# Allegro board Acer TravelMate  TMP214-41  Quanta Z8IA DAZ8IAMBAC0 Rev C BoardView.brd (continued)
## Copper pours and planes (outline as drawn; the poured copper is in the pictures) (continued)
N18922914 on TOP (solid shape): 125.44,199.8 125.65,199.74 125.85,199.8 126.38,199.8 126.43,199.8 126.49,199.79 126.75,199.54 126.75,199.29 126.63,199.17 126.49,199.17 126.35,199.03 126.35,198.34 126.46,198.24 127.05,198.24 127.1,198.18 127.1,197.85 126.81,197.55 126.11,197.55 126.01,197.44 125.31,197.44 125.2,197.34 123.58,197.34 123.44,197.48 123.44,198.04 123.64,198.24 124.57,198.24 124.7,198.15 124.86,198.11 125.13,198.23 125.24,198.5 125.19,198.68 125.06,198.82 125.06,199.64 125.22,199.8
N22317721 on TOP (solid shape): 34.49,45.66 34.49,45.13 34.58,45.04 35.69,45.04 35.74,44.98 35.74,44.34 35.69,44.29 34.64,44.29 34.3,43.95 33.59,43.95 33.47,44.07 33.47,45.48 33.74,45.75 34.4,45.75
N22317721 on BOTTOM (solid shape): 34.51,45.67 34.51,44.14 34.31,43.94 32.46,43.94 32.14,44.26 32.14,45.18 32.72,45.77 34.41,45.77
N23734831 on BOTTOM (solid shape): 92.8,194.84 92.95,194.71 93.13,194.67 93.32,194.71 93.46,194.84 93.61,194.84 93.62,194.83 97.28,194.83 97.66,194.44 97.66,194.39 97.74,194.21 97.91,194.13 98.21,194.13 98.25,194.14 98.28,194.14 98.29,194.13 98.29,193.47 97.96,193.14 97.4,193.14 97.35,193.15 97.3,193.15 97.08,193.09 96.93,192.91 95.75,192.91 95.55,192.71 95.55,191.13 95.45,191.03 94.18,191.03 94.07,191.14 94.07,192.55 94.38,192.86 94.38,193.21 94.13,193.47 93.57,193.47 93.28,193.18 92.62,193.18 92.35,192.91 92.35,192.45 92.3,192.4 90.62,192.4 90.62,192.96 90.02,193.57 89.71,193.57 89.58,193.7 89.58,194.71 89.71,194.84
N24199172 on TOP (solid shape): 9.44,12.72 9.44,12.34 9.32,12.21 8.81,12.21 8.55,12.47 8.52,12.47 8.49,12.49 7.73,12.49 7.7,12.47 7.54,12.47 7.41,12.34 7.41,11.58 6.78,10.94 6.4,10.94 6.27,11.07 6.27,11.45 6.78,11.96 6.78,12.47 7.28,12.98 9.19,12.98
N24507636 on BOTTOM (solid shape): 9.7,41.18 9.7,37.11 10.08,36.73 11.22,36.73 11.98,35.96 11.98,35.71 11.86,35.58 11.35,35.58 11.2,35.43 8.43,35.43 8.3,35.56 8.3,35.84 8.3,35.84 8.17,35.96 8.17,37.49 7.08,37.49 6.83,37.23 6.32,37.23 6.07,37.48 6.07,38.26 6.46,38.26 6.54,38.28 6.6,38.35 6.62,38.35 6.78,38.5 6.78,39.65 6.9,39.77 8.17,39.77 8.3,39.9 8.3,41.17 8.56,41.43 9.44,41.43
N24690147 on TOP (solid shape): 130.35,187.73 130.35,187.47 130.09,187.22 129.33,187.22 129.2,187.09 129.2,186.84 129.08,186.71 128.82,186.71 128.57,186.97 128.57,187.73 128.7,187.86 130.22,187.86
N24742107 on TOP (solid shape): 95.46,187.12 95.68,187.05 95.9,187.12 96.15,187.12 96.17,187.11 96.26,187.08 96.35,187.07 96.44,187.08 96.53,187.11 96.54,187.12 96.69,187.12 96.99,186.81 96.99,186.61 97.07,186.43 97.25,186.36 97.44,186.36 97.55,186.25 97.55,185.66 96.77,184.88 96.69,184.88 96.68,184.89 96.58,184.94 96.46,184.96 96.34,184.94 96.23,184.88 95.17,184.88 95.07,184.98 95.07,185.07 95.76,185.07 95.76,185.27 95.07,185.27 95.07,185.57 95.13,185.57 95.14,185.56 95.25,185.5 95.37,185.48 95.75,185.86 95.37,186.24 95.29,186.23 95.21,186.21 95.11,186.21 95.07,186.3 95.07,187.05 95.11,187.06 95.18,187.08 95.25,187.12
N24742107 on BOTTOM (solid shape): 96.72,186.18 96.72,186.04 96.76,185.94 96.87,185.89 97.98,185.89 98.24,185.62 98.24,184.83 98.16,184.75 97.82,184.75 97.73,184.76 97.65,184.75 96.93,184.75 96.85,184.83 96.85,184.84 96.7,185.04 96.46,185.12 96.38,185.11 96.31,185.09 96.03,185.09 95.91,185.21 95.91,186.17 96.05,186.31 96.58,186.31
N24846908 on TOP (solid shape): 34.87,175.97 34.95,175.89 34.95,175.49 34.91,175.45 33.49,175.45 33.34,175.3 33.34,174.34 32.44,173.45 31.98,173.45 31.87,173.56 31.87,173.92 32.44,174.49 32.44,175.89 32.52,175.97 33.96,175.97
N24846932 on TOP (solid shape): 28.86,175.42 28.94,175.42 29.02,175.42 29.11,175.45 31.75,175.45 32.18,175.02 32.18,174.55 32.09,174.46 31.6,174.46 31.25,174.8 30.89,174.8 30.86,174.81 30.3,174.81 30.27,174.8 30.04,174.8 29.44,174.2 29.44,173.71 28.96,173.24 27.41,173.24 27.3,173.34 27.3,175.31 27.44,175.45 28.78,175.45
N24915888 on TOP (solid shape): 30.02,149.63 30.02,148.36 29.89,148.23 29.26,148.23 29.13,148.1 28.75,148.1 28.66,148.19 28.66,148.53 29.38,149.25 29.38,149.5 29.76,149.88
N25430994 on TOP (solid shape): 18.95,148.1 18.95,147.31 18.13,146.49 17.39,146.49 16.34,145.44 14.65,145.44 14.07,146.02 14.07,146.68 14.3,146.92 17.06,146.92 18.3,148.16 18.89,148.16
N26318025 on BOTTOM (solid shape): 36.88,194.33 36.88,193.44 36.11,192.68 34.59,192.68 34.34,192.43 34.24,192.38 34.2,192.27 34.2,191.61 34.08,191.49 33.5,191.49 33.32,191.67 33.32,192.81 33.7,193.19 35.35,193.19 35.48,193.32 35.48,194.33 35.61,194.46 36.75,194.46
N26402629 on TOP (solid shape): 38.76,136.83 38.75,136.8 38.74,136.77 38.74,136.74 38.74,136.36 38.77,136.27 38.84,136.21 38.87,136.2 38.87,135.42 38.76,135.31 38.01,135.31 37.78,135.07 37.78,134.09 38.07,133.79 38.99,133.79 39.11,133.66 39.11,132.4 39.02,132.31 35.26,132.31 34.97,132.59 34.97,135.23 34.42,135.78 34.42,136.73 34.56,136.87 38.72,136.87
N30140264 on TOP (solid shape): 150.54,213.76 151.43,213.76 151.58,213.61 151.58,213.59 151.67,213.36 151.86,213.2 151.86,213.04 151.94,212.96 151.94,210.97 152.32,210.59 152.32,209.06 152.19,208.94 151.68,208.94 151.56,209.06 151.56,210.21 151.18,210.59 151.18,211.48 151.43,211.73 151.43,212.75 151.31,212.87 151.31,212.88 151.16,213.08 150.92,213.15 150.85,213.15 150.78,213.13 149.65,213.13 149.47,213.31 149.47,213.92 150.39,213.92
N30330849 on TOP (solid shape): 162.86,164.68 163.43,164.68 163.75,164.36 163.75,162.33 167.05,159.03 167.05,155.71 166.99,155.6 166.97,155.47 166.99,155.35 167.04,155.24 167.16,155.13 167.3,155.07 167.32,155.07 167.56,154.83 167.56,153.31 168.67,152.2 168.67,150.29 168.42,150.04 167.36,150.04 167.34,150.06 167.29,150.1 167.23,150.11 166.57,150.11 166.53,150.1 166.49,150.09 166.43,150.07 166.37,150.1 166.33,150.13 166.28,150.16 166.18,150.21 166.06,150.23 165.86,150.18 165.72,150.04 164.86,150.04 164.76,150.14 164.76,151.63 164.92,151.79 164.92,151.96 164.92,151.96 164.92,154.47 165.26,154.82 165.26,157.46 165.27,157.46 165.27,157.48 163.77,158.98 161.72,158.98 161.21,159.48 161.21,161.06 160.57,161.69 159.18,161.69 159.05,161.82 159.05,165.12 159.3,165.38 162.16,165.38
N30330849 on BOTTOM (solid shape): outline of 110 points within 163.62,149.94 168.65,156.7
N30442036 on TOP (solid shape): 36.38,161.99 36.58,161.99 36.58,162.73 38.4,162.73 38.57,162.57 38.57,161.59 38.45,161.47 38.45,159.46 38.27,159.28 36.88,159.28 36.54,159.61 36.54,160.92 36.44,161.02 36.44,161.04 36.38,161.14 36.29,161.2 36.25,161.22 36.25,161.61 36.24,161.69 36.19,161.76 36.11,161.85 36.11,161.9 36.14,161.99 36.18,161.99 36.18,162.73 36.38,162.73
N30587125 on BOTTOM (solid shape): 57.58,182.04 57.58,180.46 58.9,179.14 59,179.14 59,178.33 58.31,178.33 58.31,179.04 57.65,179.7 56.87,179.7 56.76,179.8 56.76,182.06 57.55,182.06
N31076875 on BOTTOM (solid shape): 203.71,127.76 203.78,127.71 203.86,127.69 205.07,127.69 205.76,127 205.76,125.63 205.61,125.48 204.68,125.48 204.21,125.95 203.17,125.95 202.83,126.29 202.38,126.29 201.79,126.88 201.79,127.83 202.49,127.83 202.49,128.02 201.79,128.02 201.79,128.19 201.82,128.23 202.49,128.23 202.49,128.24 203.23,128.24
N31353100 on TOP (solid shape): 35.24,140.85 35.24,138.99 35.1,138.86 34.05,138.86 33.98,138.92 33.98,140.89 34.11,141.02 35.07,141.02
N31870175 on TOP (solid shape): 233.6,122.32 233.6,121.23 234.37,120.46 234.37,118.91 234.25,118.79 233.85,118.79 233.71,118.92 233.71,119.54 233.72,119.55 233.56,119.7 233.56,119.75 232.96,120.35 232.96,122.32 233.09,122.45 233.47,122.45
N32485009 on TOP (solid shape): 52.51,193.06 52.57,192.92 52.56,192.85 52.51,192.79 51.77,192.04 51.77,191.9 51.89,191.78 52.44,191.78 52.7,192.03 53.13,192.03 53.84,192.74 54.81,192.74 54.9,192.83 54.96,192.87 55.04,192.89 55.17,192.83 55.23,192.7 55.21,192.62 55.17,192.56 54.97,192.36 54,192.36 53.29,191.65 52.86,191.65 52.66,191.46 52.6,191.41 52.52,191.4 51.43,191.4 51.36,191.41 51.3,191.44 51.3,192.12 52.24,193.06 52.31,193.1 52.38,193.12
N33144601 on BOTTOM (solid shape): 221.15,123.94 221.15,123.34 221.03,123.21 218.53,123.21 218.43,123.31 218.43,123.93 218.51,124.01 221.08,124.01
N33144601 on BOTTOM (solid shape): 224.53,135.82 224.53,133.6 224.18,133.25 221.39,133.25 221.01,133.62 221.01,134.23 222.54,134.23 222.68,134.36 222.68,135.58 222.64,135.62 221.01,135.62 221.01,136.23 224.12,136.23
N33144601 on IN2 (solid shape): 224.58,134.08 224.58,128.55 221.2,125.17 221.2,123.39 221.03,123.21 219.88,123.21 219.76,123.34 219.76,125.76 222.82,128.83 222.82,134.15 223.01,134.34 224.33,134.34
N33147251 on TOP (solid shape): 89.3,175.33 89.3,175.26 89.25,175.21 88.79,175.21 88.62,175.03 88.62,173.68 88.18,173.25 88.18,171.98 88.06,171.85 87.42,171.85 87.29,171.98 87.29,172.74 87.55,173 87.55,174.24 87.68,174.37 87.98,174.37 88.22,174.61 88.22,174.8 88.26,174.84 88.26,175.38 89.25,175.38
N34933887 on BOTTOM (solid shape): 13.63,38.76 14.4,38.76 14.52,38.63 14.52,37.51 14.14,37.13 13.36,37.13 12.87,37.61 12.87,38.76 13,38.88 13.51,38.88
N35745601 on TOP (solid shape): 147.24,131.47 148.25,131.47 148.38,131.34 148.38,130.2 148.13,129.94 147.37,129.94 147.37,130.53 146.68,131.21 146.68,131.47 146.81,131.59 147.11,131.59
N36874581 on TOP (solid shape): 62.12,180.87 62.12,178.52 62.15,178.5 62.15,177.01 62.55,176.61 62.58,176.53 62.55,176.46 62.46,176.33 62.43,176.17 62.48,175.97 62.62,175.82 62.62,175 62.71,174.92 62.71,174.72 62.58,174.6 60.93,174.6 60.19,175.33 60.19,176.37 60.88,177.06 60.88,177.92 61.18,178.23 61.18,179.65 60.6,180.24 60.6,180.87 60.83,181.1 61.89,181.1
N45124268 on TOP (solid shape): 30.28,177.37 30.23,177.33 30.22,177.33 30.04,177.18 29.97,176.95 30.08,176.67 30.39,176.53 30.4,176.49 30.4,176.1 29.93,175.63 29.44,175.63 29.37,175.67 29.34,175.75 29.35,175.79 29.35,175.82 28.94,176.23 28.54,175.82 28.54,175.79 28.54,175.75 28.52,175.67 28.44,175.63 26.54,175.63 26.52,175.66 26.52,177.37 26.58,177.44 30.22,177.44
N47271970 on BOTTOM (solid shape): 123.36,178.2 123.36,177.95 122.93,177.52 122.93,176.65 122.88,176.61 121.53,176.61 120.57,177.57 120.57,178.2 120.7,178.33 123.24,178.33
N47707814 on BOTTOM (solid shape): 82.96,187.91 82.96,187.29 82.89,187.21 81.81,187.21 81.7,187.1 81.7,186.96 81.63,186.91 81.61,186.82 81.61,186.5 81.48,186.38 81.46,186.34 81.45,186.29 80.97,185.81 80.2,185.81 80.09,185.7 79.3,185.7 79.04,185.8 78.78,185.7 77.12,185.7 76.95,185.88 76.95,187.72 76.99,187.76 77.91,187.76 78.01,187.66 78.01,186.67 78.16,186.52 80.73,186.52 81.07,186.86 81.07,187.76 81.35,188.04 82.83,188.04
N47708170 on BOTTOM (solid shape): 86.15,187.47 86.15,187.09 86.02,186.97 84.25,186.97 84.12,187.09 84.12,187.47 84.25,187.6 86.02,187.6

Small or netless copper shapes (teardrops, artwork), in the pictures only: 84 on TOP, 102 on BOTTOM, 1 on IN1, 33 on IN2, 1 on IN4

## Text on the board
Ref Des/Silkscreen Bottom: Please do not print out the lines with 0.39mils/0.01mm in width | Acer Incorp. | MODEL:Z8IA | DAZ8IAMBAC0 REV:C
User.Comments: 16x28 | 33x37 | 87x106
Ref Des/Silkscreen Top: DAZ8IAMBAC0 REV:C | Please do not print out the lines with 0.39mils/0.01mm in width | Acer Incorp.
User.12: ADOGND | TYPEC1_USB0 | +5VPCU | GND | +1.8V_DEEP_SUS | +VCCIN_AUX | +VCCIN | +VAC_IN | +1.8V_S5 | +5V_S5 | +5V | +1V8_GFX_MAIN | +1V8_AON | +VGPU_CORE | +3V
User.31: GND | ADOGND
User.45: Excess check:Jul 12 10:14:31 2019 | No Route Under Component:Jul 12 10:34:17 2019 | PadStack_Check:Jul 12 10:05:37 2019 | TP check:Jul 12 10:05:44 2019 | XY-Check acute:Jul 12 10:20:48 2019 | XY-Create nettxt:Jul 09 16:31:07 2019 | XY-Create plane:Jul 12 09:49:40 2019 | XY-Cross plane-BOTTOM-SGND2:Jul 12 10:29:36 2019 | XY-Cross plane-IN1-SGND:Jul 12 10:29:09 2019 | XY-Cross plane-IN1-SVCC:Jul 12 10:29:05 2019 | XY-Cross plane-IN2-SVCC:Jul 12 10:29:13 2019 | XY-Cross plane-IN3-SGND1:Jul 12 10:29:18 2019 | XY-Cross plane-IN4-SGND1:Jul 12 10:29:30 2019 | XY-Cross plane-IN4-SGND2:Jul 12 10:29:24 2019 | XY-Cross plane-TOP-SGND:Jul 12 10:29:01 2019 | XY-Dxf to pin check:Jul 12 10:11:34 2019 | XY-Etch cross-IN2-IN3:Jul 12 10:29:12 2019 | XY-Etch ref-BOTTOM-SGND2:Jul 12 10:29:47 2019 | XY-Etch ref-IN1-SGND:Jul 12 10:29:12 2019 | XY-Etch ref-IN1-SVCC:Jul 12 10:29:09 2019 | XY-Etch ref-IN2-SVCC:Jul 12 10:29:18 2019 | XY-Etch ref-IN3-SGND1:Jul 12 10:29:23 2019 | XY-Etch ref-IN4-SGND1:Jul 12 10:29:36 2019 | XY-Etch ref-IN4-SGND2:Jul 12 10:29:30 2019 | XY-Etch ref-TOP-SGND:Jul 12 10:29:05 2019 | XY-Excess check:Jul 12 10:14:31 2019 | XY-NO Route Under Component:Jul 12 10:34:17 2019 | XY-Outline check:Jul 12 10:34:23 2019 | XY-PadStack_Check:Jul 12 10:05:37 2019 | XY-Plane net check:Jul 12 10:12:49 2019 | XY-Prop check:Jul 12 10:28:38 2019 | XY-TP check:Jul 12 10:05:44 2019 | XY-shape min check:Jul 12 10:03:21 2019 | XY-via check:Jul 12 10:31:33 2019 | check acute:Jul 12 10:20:48 2019 | cross plane-BOTTOM-SGND2:Jul 12 10:29:36 2019 | cross plane-IN1-SGND:Jul 12 10:29:09 2019 | cross plane-IN1-SVCC:Jul 12 10:29:05 2019 | cross plane-IN2-SVCC:Jul 12 10:29:13 2019 | cross plane-IN3-SGND1:Jul 12 10:29:18 2019 | cross plane-IN4-SGND1:Jul 12 10:29:30 2019 | cross plane-IN4-SGND2:Jul 12 10:29:24 2019 | cross plane-TOP-SGND:Jul 12 10:29:01 2019 | dxf to pin check:Jul 12 10:11:34 2019 | etch cross-IN2-IN3:Jul 12 10:29:12 2019 | etch ref-BOTTOM-SGND2:Jul 12 10:29:47 2019 | etch ref-IN1-SGND:Jul 12 10:29:12 2019 | etch ref-IN1-SVCC:Jul 12 10:29:09 2019 | etch ref-IN2-SVCC:Jul 12 10:29:18 2019 | etch ref-IN3-SGND1:Jul 12 10:29:23 2019 | etch ref-IN4-SGND1:Jul 12 10:29:36 2019 | etch ref-IN4-SGND2:Jul 12 10:29:30 2019 | etch ref-TOP-SGND:Jul 12 10:29:05 2019 | outline check:Jul 12 10:34:23 2019 | plane net check:Jul 12 10:12:49 2019 | prop check:Jul 12 10:28:38 2019 | shape min check:Jul 12 10:03:21 2019 | via check:Jul 12 10:31:33 2019 | FIGURE | TYPE | Circle | Oblong | Rectangle | SIZE | 8.0 | 10.0 | 12.0 | 14.0 | 22.0 | 28.0 | 32.0 | 35.0 | 118.0 | 126.0 | 146.0 | 177.0 | 240.0 | 24.0 | 38.0 | 39.0 | 41.0 | 43.0 | 47.0 | 63.0 | 67.0 | 87.0 | 49.0x20.0 | 59.0x20.0 | 59.0x28.0 | 63.0x31.0 | 71.0x31.0 | 73.0x22.0 | 75.0x39.0 | 91.0x28.0 | 98.0x24.0 | 102.0x31.0 | 118.0x20.0 | 157.0x157.0 | DRILL CHART: TOP to BOTTOM | ALL UNITS ARE IN MILS | PLATED | NON-PLATED | ROTATION | - | 90.000 | 0.000 | QTY | 53 | 6602 | 9 | 5 | 249 | 19 | 15 | 18 | 8 | 10 | 3 | 1 | 2 | 7014 | 6 | 4 | 38 | TOTAL HOLES:
